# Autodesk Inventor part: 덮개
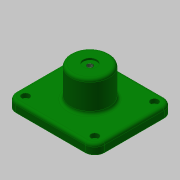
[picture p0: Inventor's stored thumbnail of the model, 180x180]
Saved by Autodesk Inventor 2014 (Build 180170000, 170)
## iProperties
Created: 2017-08
Part Number: 덮개
Material: 알루미늄 6061
Document SubType Name: Modeling
Designer: mduedu
Density: 1 g/cm^3
Appearance: 진녹색
Author: mduedu
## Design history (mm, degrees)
sketch "스케치1"
  geometry: L1 (46, -41)-(-46, -41); L2 (-46, -41)-(-46, 41); L3 (-46, 41)-(46, 41); L4 (46, 41)-(46, -41); 1 further point
  constraints: 8 end point, 2 parallel, 1 horizontal, 1 perpendicular
  dimensions: "d0" = 92 distance of L2.end L3.end; "d2" = 82 distance of L1.end L2.end; "d3" = 41 distance from line of L3 point (0, 0) (= 0.5 x d2); "d4" = 46 distance from line of point (0, 0) L4 (= 0.5 x d0)
extrude "돌출1" new body sketch "스케치1" distance "d5" = 10; taper "d6" = 0 deg
sketch "스케치2"
  geometry: C1 r 20 at (0, 0); 1 further point
  constraints: 1 centre point, 1 coincident
  dimensions: "d55" = 40 diameter of C1
extrude "돌출2" join sketch "스케치2" distance "d9" = 32; taper "d10" = 0 deg
sketch "스케치3"
  geometry: L1 (-26, -26)-(26, -26); L2 (26, -26)-(26, 26); L3 (26, 26)-(-26, 26); L4 (-26, 26)-(-26, -26); L5 (-26, -26)-(26, 26); L6 (26, -26)-(-26, 26); 1 further point
  constraints: 12 end point, 2 midpoint, 2 parallel, 2 perpendicular, 1 horizontal
  dimensions: "d11" = 52 distance of L3.end L2.end
extrude "돌출3" join sketch "스케치3" distance "d12" = 6; taper "d13" = 0 deg
sketch "스케치4"
  geometry: L1 (-17, -17)-(17, -17); L2 (17, -17)-(17, 17); L3 (17, 17)-(-17, 17); L4 (-17, 17)-(-17, -17); L5 (-17, -17)-(17, 17); L6 (17, -17)-(-17, 17); 1 further point
  constraints: 12 end point, 2 midpoint, 2 parallel, 2 perpendicular, 1 horizontal
  dimensions: "d14" = 34 distance of L2.end L3.end
extrude "돌출4" cut sketch "스케치4" distance "d16" = 5; taper "d17" = 0 deg
sketch "스케치5"
  geometry: C1 r 9 at (0, 0); 1 further point
  constraints: 1 centre point, 1 coincident
  dimensions: "d18" = 18 diameter of C1
extrude "돌출5" cut sketch "스케치5" distance "d19" = 34; taper "d20" = 0 deg
sketch "스케치6"
  geometry: 2 further points
  constraints: 1 coincident
hole "구멍1" sketch "스케치6" at (0, 0) diameter "d21" = 5.917; stored, may be unused: countersink angle "d25" = 90 deg, drill point angle "d27" = 118 deg; dims "d22" = 6, "d23" = 14, "d24" = 2, "d26" = 8
fillet "모깎기1" dims "d36" = 10
fillet "모깎기3" dims "d38" = 3
fillet "모깎기4" dims "d39" = 3
fillet "모깎기5" dims "d40" = 3
chamfer "모따기1" distance "d41" = 1; stored, may be unused: second distance "d42" = 2, angle "d43" = 45 deg
fillet "모깎기6" dims "d44" = 3
fillet "모깎기7" dims "d45" = 3
fillet "모깎기8" dims "d46" = 3
sketch "스케치8"
  geometry: A1 r 10 centre (-36, -31) between (-46, -31) and (-36, -41) reference; A2 r 10 centre (-36, 31) between (-36, 41) and (-46, 31) reference; A3 r 10 centre (36, 31) between (46, 31) and (36, 41) reference; A4 r 10 centre (36, -31) between (36, -41) and (46, -31) reference; 5 further points
  constraints: 4 coincident
sketch "스케치9"
  geometry: 4 further points
  constraints: 4 other
hole "구멍3" sketch "스케치9" at (-36, -31), (-36, 31), (36, 31), (36, -31) diameter "d48" = 4.5; stored, may be unused: countersink angle "d52" = 90 deg, drill point angle "d54" = 0 deg; dims "d49" = 6, "d50" = 8, "d51" = 4.6, "d53" = 8
node "솔리드1"
